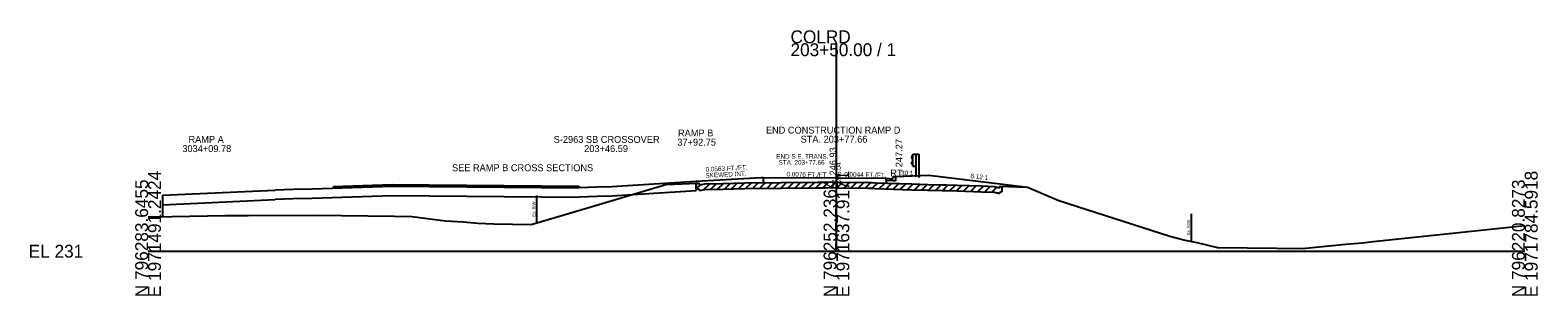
# Model space of a CAD drawing. Extents: x -26 to 1971520, y -10 to 796285.
# Drawn here: x 1274.3 to 1602.8, y 1490.3 to 1548.1 of the extents above; entities that cross this region are included whole.
import ezdxf

# ---------------------------------------------------------------- set-up
doc = ezdxf.new("R2010")
doc.units = 0
for name, color, linetype in [('RD_GPK_XS_Cell', 7, 'Continuous'), ('RD_XS_Base', 7, 'Continuous'), ('RD_XS_CurbBase', 7, 'Continuous'), ('RD_XS_CurbTop', 7, 'Continuous'), ('RD_XS_ExGround', 7, 'Continuous'), ('RD_XS_ExPaveRet', 7, 'Continuous'), ('RD_XS_ExRW', 7, 'Continuous'), ('RD_XS_GR', 7, 'Continuous'), ('RD_XS_MedBbase', 7, 'Continuous'), ('RD_XS_Misc_Line', 7, 'Continuous'), ('RD_XS_Pave', 7, 'Continuous'), ('RD_XS_PaveOvlay', 7, 'Continuous'), ('RD_XS_PaveShd', 7, 'Continuous'), ('RD_XS_TieSlope', 7, 'Continuous'), ('RD_XS_TX_Elev_EX', 7, 'Continuous'), ('RD_XS_TX_Elev_PR', 7, 'Continuous'), ('RD_XS_TX_MkPT', 7, 'Continuous'), ('RD_XS_TX_Notes', 7, 'Continuous'), ('RD_XS_TX_Slope', 7, 'Continuous'), ('RD_XS_TX_Station', 7, 'Continuous'), ('RD_XS_TX_TOC', 7, 'Continuous')]:
    doc.layers.add(name, color=color, linetype=linetype)

msp = doc.modelspace()

# ---------------------------------------------------------------- linework, layer by layer
at = {"layer": 'RD_GPK_XS_Cell'}
for p, q in [((1450, 1500), (1450, 1545.22)), ((1300, 1500), (1450, 1500)), ((1450, 1500), (1600, 1500))]:
    msp.add_line(p, q, dxfattribs=at)
at = {"layer": 'RD_XS_Base'}
for p, q in [((1460.87, 1515.85), (1460.87, 1515.87)), ((1460.87, 1515.36), (1460.87, 1515.86)), ((1460.87, 1515.36), (1460.87, 1514.81)), ((1303.16, 1512.16), (1303.16, 1507.54)), ((1333.61, 1511.48), (1327.71, 1511.22)), ((1333.61, 1511.48), (1353.2, 1512.14)), ((1353.2, 1512.14), (1393.85, 1511.73)), ((1399.87, 1511.97), (1393.85, 1511.73)), ((1399.87, 1511.97), (1419.47, 1513.2)), ((1303.16, 1510.12), (1327.71, 1511.22))]:
    msp.add_line(p, q, dxfattribs=at)
at = {"layer": 'RD_XS_CurbBase'}
for p, q in [((1462.3, 1515.27), (1460.87, 1515.36)), ((1462.89, 1515.27), (1462.3, 1515.27)), ((1462.89, 1516.27), (1462.89, 1515.27))]:
    msp.add_line(p, q, dxfattribs=at)
at = {"layer": 'RD_XS_CurbTop'}
for p, q in [((1460.87, 1515.87), (1460.87, 1515.85)), ((1460.87, 1515.86), (1462.3, 1515.77)), ((1462.3, 1515.77), (1462.39, 1516.27)), ((1462.39, 1516.27), (1462.89, 1516.27))]:
    msp.add_line(p, q, dxfattribs=at)
at = {"layer": 'RD_XS_ExGround'}
msp.add_lwpolyline([(1300, 1507.46), (1301.37, 1507.5), (1316.77, 1507.79), (1321.82, 1507.79), (1336.31, 1507.83), (1353.69, 1507.62), (1357.45, 1507.56), (1364.83, 1506.59), (1368.68, 1506.36), (1371.86, 1506.08), (1375.35, 1505.97), (1383.49, 1505.81), (1387.2, 1506.93), (1398.2, 1510.19), (1412.85, 1514.51), (1417.95, 1514.76), (1420.03, 1514.83), (1420.13, 1514.43), (1420.61, 1514.49), (1421.31, 1514.65), (1425.28, 1514.76), (1430.05, 1514.88), (1446.01, 1515.03), (1447.41, 1515.04), (1447.65, 1515.07), (1450.25, 1515.04), (1457.02, 1514.95), (1457.75, 1514.93), (1458.44, 1514.89), (1466.44, 1514.63), (1469.92, 1514.52), (1473.01, 1514.43), (1474, 1514.42), (1476.33, 1514.39), (1481.62, 1514.19), (1484.38, 1514.09), (1484.76, 1513.99), (1485.55, 1513.78), (1485.65, 1514.18), (1489.41, 1514.02), (1491.65, 1513.92), (1498.48, 1511), (1522.65, 1503.25), (1526, 1502.39), (1528.56, 1501.87), (1533.01, 1500.82), (1546.05, 1500.68), (1551.59, 1500.59), (1561.03, 1501.56), (1564.63, 1501.84), (1566.93, 1502.13), (1595.31, 1505.1), (1600, 1505.58)], dxfattribs=at)
at = {"layer": 'RD_XS_ExPaveRet'}
for p, q in [((1419.47, 1513.56), (1419.47, 1514.81)), ((1419.47, 1513.56), (1420.03, 1513.58)), ((1420.03, 1513.58), (1420.13, 1513.18)), ((1420.13, 1513.18), (1420.61, 1513.24)), ((1420.61, 1513.24), (1421.31, 1513.4)), ((1421.31, 1513.4), (1425.28, 1513.51)), ((1425.28, 1513.51), (1430.05, 1513.63)), ((1430.05, 1513.63), (1446.01, 1513.78)), ((1446.01, 1513.78), (1447.41, 1513.79)), ((1447.41, 1513.79), (1447.65, 1513.82)), ((1447.65, 1513.82), (1450.25, 1513.79)), ((1450.25, 1513.79), (1457.02, 1513.7)), ((1457.02, 1513.7), (1457.75, 1513.68)), ((1457.75, 1513.68), (1458.44, 1513.64)), ((1458.44, 1513.64), (1466.44, 1513.38)), ((1466.44, 1513.38), (1469.92, 1513.27)), ((1469.92, 1513.27), (1473.01, 1513.18)), ((1473.01, 1513.18), (1474, 1513.17)), ((1474, 1513.17), (1476.33, 1513.14)), ((1476.33, 1513.14), (1481.62, 1512.94)), ((1481.62, 1512.94), (1484.38, 1512.84)), ((1484.38, 1512.84), (1484.76, 1512.74)), ((1484.76, 1512.74), (1485.55, 1512.53)), ((1485.55, 1512.53), (1485.65, 1512.93)), ((1485.65, 1512.93), (1486.04, 1512.91)), ((1486.04, 1514.16), (1486.04, 1512.91))]:
    msp.add_line(p, q, dxfattribs=at)
at = {"layer": 'RD_XS_ExRW'}
for p, q in [((1384.63, 1512.15), (1384.63, 1506.15)), ((1527.29, 1508.13), (1527.29, 1502.13))]:
    msp.add_line(p, q, dxfattribs=at)
at = {"layer": 'RD_XS_GR'}
for p, q in [((1466.66, 1520.92), (1466.39, 1520.48)), ((1466.39, 1520.48), (1466.39, 1520.37)), ((1466.39, 1520.37), (1466.66, 1519.93)), ((1466.39, 1519.23), (1466.66, 1519.67)), ((1466.39, 1519.12), (1466.39, 1519.23)), ((1466.66, 1518.68), (1466.39, 1519.12)), ((1466.66, 1521.08), (1467.33, 1521.08)), ((1466.66, 1518.52), (1466.66, 1521.08)), ((1466.66, 1518.52), (1467.33, 1518.52)), ((1467.33, 1521.08), (1467.99, 1521.08)), ((1467.33, 1521.08), (1467.33, 1516.14)), ((1467.99, 1521.08), (1467.99, 1516.03))]:
    msp.add_line(p, q, dxfattribs=at)
at = {"layer": 'RD_XS_MedBbase'}
for p, q in [((1340.41, 1514.08), (1353.2, 1514.51)), ((1340.41, 1514.08), (1340.41, 1513.75)), ((1353.2, 1514.51), (1393.85, 1514.11)), ((1393.85, 1514.11), (1393.85, 1513.77))]:
    msp.add_line(p, q, dxfattribs=at)
at = {"layer": 'RD_XS_Misc_Line'}
for p, q in [((1421, 1513.33), (1422.38, 1514.68)), ((1422.53, 1513.43), (1423.85, 1514.72)), ((1424.07, 1513.48), (1425.38, 1514.76)), ((1425.6, 1513.52), (1426.91, 1514.8)), ((1427.13, 1513.56), (1428.44, 1514.84)), ((1428.67, 1513.59), (1429.98, 1514.88)), ((1430.2, 1513.63), (1431.49, 1514.89)), ((1431.73, 1513.64), (1433.02, 1514.91)), ((1433.26, 1513.66), (1434.55, 1514.92)), ((1434.8, 1513.67), (1436.09, 1514.94)), ((1436.33, 1513.69), (1437.62, 1514.95)), ((1437.86, 1513.7), (1439.15, 1514.96)), ((1439.4, 1513.72), (1440.69, 1514.98)), ((1440.93, 1513.73), (1442.22, 1514.99)), ((1442.46, 1513.75), (1443.75, 1515.01)), ((1443.99, 1513.76), (1445.28, 1515.02)), ((1445.53, 1513.77), (1446.82, 1515.04)), ((1447.06, 1513.79), (1448.36, 1515.06)), ((1448.59, 1513.81), (1449.85, 1515.05)), ((1450.12, 1513.79), (1451.39, 1515.03)), ((1451.66, 1513.77), (1452.92, 1515.01)), ((1453.19, 1513.75), (1454.45, 1514.99)), ((1454.72, 1513.73), (1455.98, 1514.97)), ((1456.26, 1513.71), (1457.51, 1514.94)), ((1457.79, 1513.68), (1459, 1514.87)), ((1459.32, 1513.61), (1460.56, 1514.82)), ((1460.85, 1513.56), (1462.09, 1514.77)), ((1462.39, 1513.51), (1463.62, 1514.72)), ((1463.92, 1513.46), (1465.16, 1514.67)), ((1465.45, 1513.41), (1466.69, 1514.62)), ((1466.99, 1513.36), (1468.23, 1514.57)), ((1419.47, 1513.56), (1420.39, 1514.47)), ((1468.52, 1513.31), (1469.76, 1514.53)), ((1470.05, 1513.27), (1471.29, 1514.48)), ((1471.58, 1513.22), (1472.82, 1514.44)), ((1473.12, 1513.18), (1474.38, 1514.42)), ((1474.65, 1513.16), (1475.91, 1514.39)), ((1476.18, 1513.14), (1477.42, 1514.34)), ((1477.72, 1513.08), (1478.95, 1514.29)), ((1479.25, 1513.03), (1480.48, 1514.23)), ((1480.78, 1512.97), (1482.01, 1514.17)), ((1482.31, 1512.91), (1483.55, 1514.12)), ((1483.85, 1512.86), (1484.95, 1513.94))]:
    msp.add_line(p, q, dxfattribs=at)
at = {"layer": 'RD_XS_Pave'}
for p, q in [((1399.87, 1514.01), (1419.46, 1515.24)), ((1419.46, 1515.24), (1433.61, 1516.03)), ((1434, 1516.05), (1450, 1515.93)), ((1434, 1516.05), (1434, 1514.92)), ((1450, 1515.93), (1460.87, 1515.88)), ((1303.16, 1512.16), (1327.71, 1513.26))]:
    msp.add_line(p, q, dxfattribs=at)
at = {"layer": 'RD_XS_PaveOvlay'}
for p, q in [((1419.47, 1514.81), (1420.03, 1514.83)), ((1419.47, 1514.81), (1419.47, 1513.2)), ((1420.03, 1514.83), (1420.13, 1514.43)), ((1420.61, 1514.49), (1421.31, 1514.65)), ((1421.31, 1514.65), (1425.28, 1514.76)), ((1425.28, 1514.76), (1430.05, 1514.88)), ((1430.05, 1514.88), (1446.01, 1515.03)), ((1446.01, 1515.03), (1447.41, 1515.04)), ((1447.41, 1515.04), (1447.65, 1515.07)), ((1447.65, 1515.07), (1450.25, 1515.04)), ((1450.25, 1515.04), (1457.02, 1514.95)), ((1457.02, 1514.95), (1457.75, 1514.93)), ((1457.75, 1514.93), (1458.44, 1514.89)), ((1458.44, 1514.89), (1460.87, 1514.81)), ((1420.13, 1514.43), (1420.61, 1514.49))]:
    msp.add_line(p, q, dxfattribs=at)
at = {"layer": 'RD_XS_PaveShd'}
for p, q in [((1433.61, 1516.03), (1434, 1516.05)), ((1333.61, 1513.52), (1327.71, 1513.26)), ((1333.61, 1513.52), (1353.2, 1514.18)), ((1353.2, 1514.18), (1393.85, 1513.77)), ((1399.87, 1514.01), (1393.85, 1513.77))]:
    msp.add_line(p, q, dxfattribs=at)
at = {"layer": 'RD_XS_TieSlope'}
for p, q in [((1462.89, 1516.27), (1470.14, 1516.52)), ((1470.14, 1516.52), (1491.65, 1513.92))]:
    msp.add_line(p, q, dxfattribs=at)

# ---------------------------------------------------------------- texts
at = {"layer": 'RD_GPK_XS_Cell'}
for s, p in [('COLRD', (1440, 1545.22)), ('203+50.00 / 1', (1440, 1542.42)), ('EL 231', (1274, 1498.6))]:
    msp.add_text(s, height=2.8, dxfattribs=at).set_placement(p)
for s, p in [('N 796283.6455', (1300, 1490)), ('E 1971491.2424', (1302.8, 1490)), ('N 796252.2364', (1450, 1490)), ('E 1971637.9171', (1452.8, 1490)), ('N 796220.8273', (1600, 1490)), ('E 1971784.5918', (1602.8, 1490))]:
    msp.add_text(s, height=2.8, rotation=90, dxfattribs=at).set_placement(p)
at = {"layer": 'RD_XS_ExRW'}
for p in [(1384.38, 1507.53), (1527.04, 1503.51)]:
    msp.add_text('Ex. R/W ', height=0.65, rotation=90, dxfattribs=at).set_placement(p)
at = {"layer": 'RD_XS_TX_Elev_EX'}
msp.add_text('246.04', height=1, rotation=90, dxfattribs=at).set_placement((1451, 1515.04))
at = {"layer": 'RD_XS_TX_Elev_PR'}
msp.add_text(' 246.93', height=1.5, rotation=90, dxfattribs=at).set_placement((1450, 1515.92))
at = {"layer": 'RD_XS_TX_MkPT'}
msp.add_text('RT', height=1.5, dxfattribs=at).set_placement((1461.74, 1516.27))
at = {"layer": 'RD_XS_TX_Notes'}
for s, height, p in [('END CONSTRUCTION RAMP D', 1.5, (1434.63, 1525.58)), ('STA. 203+77.66', 1.5, (1442.19, 1523.61)), ('END S.E. TRANS.', 1, (1436.88, 1520.12)), ('SEE RAMP B CROSS SECTIONS', 1.5, (1366.23, 1517.4)), ('STA. 203+77.66', 1, (1437.4, 1518.81))]:
    msp.add_text(s, height=height, dxfattribs=at).set_placement(p)
at = {"layer": 'RD_XS_TX_Slope'}
for s, rotation, p in [('0.0563 FT./FT.', 3.0331, (1421.53, 1517.28)), ('SKEWED INT.', 3.0331, (1421.48, 1515.96)), ('0.0076 FT./FT.', 359.1047, (1439.11, 1516.28)), ('0.0044 FT./FT.', 358.6357, (1451.7, 1516.24)), ('30:1', 1.1458, (1464.1, 1516.48)), ('8.12:1', 352.9784, (1479.18, 1515.94))]:
    msp.add_text(s, height=1, rotation=rotation, dxfattribs=at).set_placement(p)
at = {"layer": 'RD_XS_TX_Station'}
for s, p in [('RAMP A', (1308.81, 1523.56)), ('S-2963 SB CROSSOVER', (1388.39, 1523.56)), ('37+92.75', (1415.33, 1522.96)), ('RAMP B', (1415.48, 1524.96)), ('3034+09.78', (1307.47, 1521.56)), ('203+46.59', (1395.04, 1521.56))]:
    msp.add_text(s, height=1.5, dxfattribs=at).set_placement(p)
at = {"layer": 'RD_XS_TX_TOC'}
msp.add_text('247.27', height=1.5, rotation=90, dxfattribs=at).set_placement((1464.39, 1518.27))

doc.saveas('drawing.dxf')
